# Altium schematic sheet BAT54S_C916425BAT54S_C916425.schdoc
size 127 x 101 mm
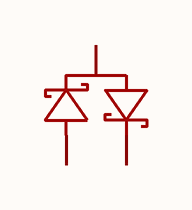
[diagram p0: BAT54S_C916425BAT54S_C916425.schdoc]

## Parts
D?  bat54s_c916425  [SOT-23-3_L2.9-W1.3-P1.90-LS2.4-BR]  (value not drawn)

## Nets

Not connected (* = marked no-connect by the designer): D? 1(A) 2(K) 3

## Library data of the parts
D? = bat54s_c916425: 二极管配置:1对串联式;正向压降(Vf):800mV@100mA;直流反向耐压(Vr):30V;整流电流:200mA;; Manufacturer: JSMSEMI(杰盛微); ManufacturerPart: BAT54S; AddInBom: yes; ModelId: c62791f0466c4ae2a892c056b845b0ca; ModelName: SOT-23-3P_L2.9-W1.3-H1.0-LS2.4-P0.95; ModelTransform: 98.425,114.173,0,180,0,0,0.0005,-0.0005,0; Diode Configuration: 1对串联式; Voltage - DC Reverse(Vr): 30V; Current - Rectified: 200mA; Reverse Leakage Current (Ir): 2uA@25V; Non-Repetitive Peak Forward Surge Current: 600mA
